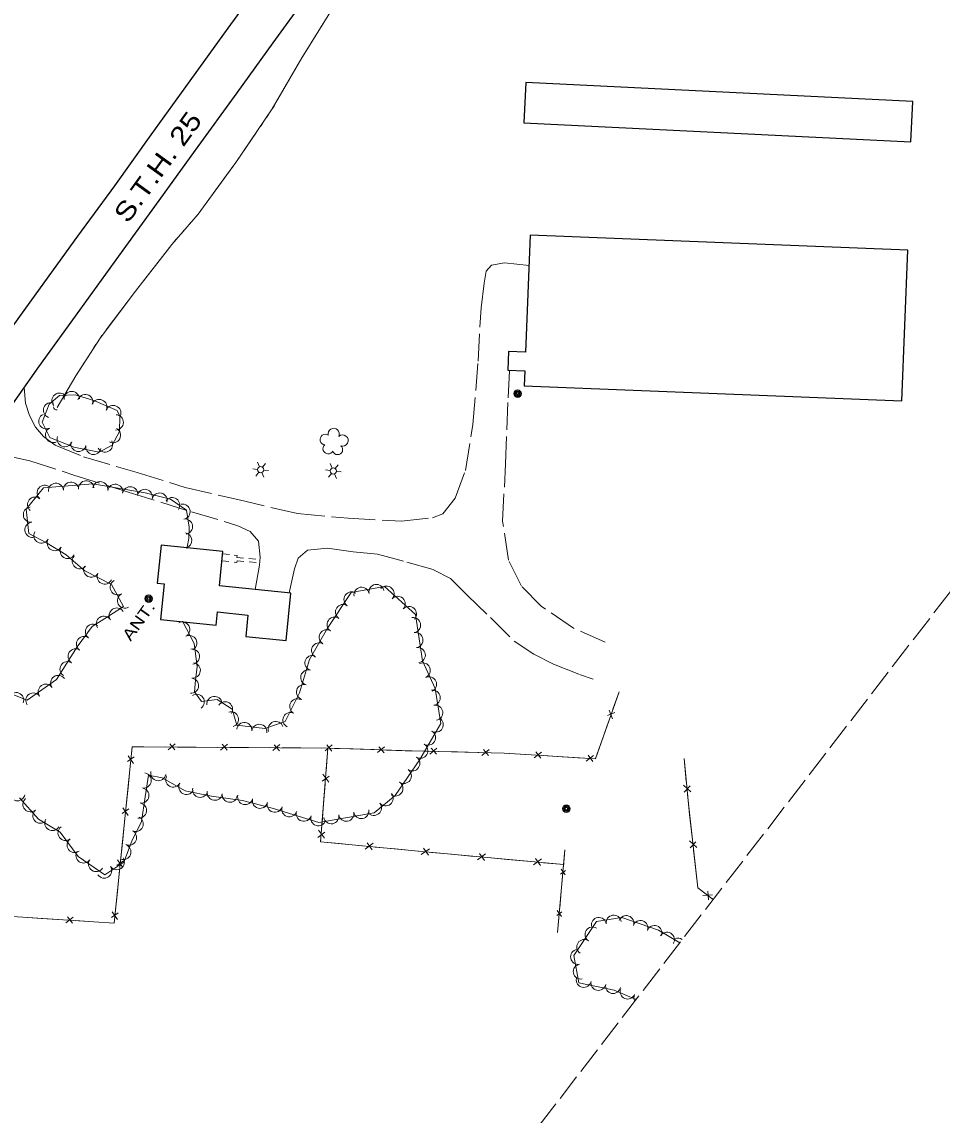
# Model space of a CAD drawing. Extents: x 299311 to 301657, y 49513 to 51866.
# Drawn here: x 300509 to 300996, y 50034 to 50612 of the extents above; entities that cross this region are included whole.
import ezdxf

# ---------------------------------------------------------------- set-up
doc = ezdxf.new("R2010")
doc.units = 0
doc.header["$LTSCALE"] = 2.4
doc.linetypes.add('LONG_DASHED', pattern=[7.5, 6, -1.5])
doc.linetypes.add('SHORT_DASHED', pattern=[2.7, 1.5, -1.2])
for name, color, linetype, lineweight in [('11', 7, 'Continuous', 25), ('12', 7, 'Continuous', 25), ('14', 7, 'Continuous', 13), ('15', 7, 'Continuous', 13), ('17', 7, 'LONG_DASHED', 13), ('18', 7, 'Continuous', 13), ('19', 7, 'Continuous', 13), ('4', 7, 'Continuous', 13)]:
    doc.layers.add(name, color=color, linetype=linetype, lineweight=lineweight)

msp = doc.modelspace()

# ---------------------------------------------------------------- linework, layer by layer
at = {"layer": '11'}
for points in [[(300449.171, 50372.95), (300462.402, 50391.823), (300478.238, 50414.348), (300497.847, 50441.838), (300516.893, 50468.271), (300538.883, 50498.768), (300558.362, 50525.367), (300577.633, 50552.405), (300598.2, 50580.809), (300618.37, 50608.824), (300640.297, 50638.797)], [(300287.176, 50107.164), (300311.291, 50140.598), (300331.977, 50169.98), (300349.427, 50194.729), (300366.089, 50218.225), (300384.892, 50244.576), (300409.609, 50278.747), (300427.494, 50303.203), (300456.56, 50343.148), (300479.329, 50374.693), (300497.325, 50400.091), (300518.311, 50429.548), (300539.854, 50459.658), (300560.519, 50488.121), (300581.893, 50517.65), (300601.128, 50544.137), (300623.029, 50574.5), (300642.077, 50601.015), (300659.645, 50625.084)]]:
    msp.add_lwpolyline(points, dxfattribs=at)
at = {"layer": '12'}
for points in [[(300774.69, 50558.683), (300979.211, 50548.544), (300980.269, 50569.887), (300775.748, 50580.026)], [(300774.842, 50419.534), (300974.479, 50411.65), (300977.626, 50491.338), (300778.066, 50499.218), (300775.625, 50437.41), (300766.593, 50437.767), (300766.202, 50427.871), (300775.157, 50427.517)], [(300582.61, 50296.002), (300612.086, 50293.017), (300612.79, 50299.969), (300628.819, 50298.346), (300627.674, 50287.037), (300648.976, 50284.88), (300651.516, 50309.965), (300613.769, 50313.787), (300615.615, 50332.011), (300582.846, 50335.33), (300580.806, 50315.187), (300584.515, 50314.811)]]:
    msp.add_lwpolyline(points, close=True, dxfattribs=at)
at = {"layer": '14'}
for p, q in [((300633.935, 50375.396), (300631.367, 50375.763)), ((300634.556, 50373.921), (300632.982, 50371.848)), ((300634.933, 50376.773), (300633.915, 50379.182)), ((300636.538, 50376.53), (300638.061, 50378.538)), ((300637.199, 50374.972), (300639.693, 50374.714)), ((300672.327, 50374.734), (300669.759, 50375.101)), ((300673.325, 50376.111), (300672.307, 50378.52)), ((300674.93, 50375.868), (300676.453, 50377.876)), ((300675.591, 50374.31), (300678.085, 50374.052)), ((300636.209, 50373.669), (300637.195, 50371.285)), ((300672.948, 50373.259), (300671.374, 50371.186)), ((300674.601, 50373.007), (300675.587, 50370.623))]:
    msp.add_line(p, q, dxfattribs=at)
for centre, radius in [((300771.402, 50415.413), 2.018), ((300771.39, 50415.418), 1.518), ((300771.426, 50415.4), 1.008), ((300771.42, 50415.409), 0.502), ((300635.563, 50375.211), 1.641), ((300673.955, 50374.549), 1.641), ((300576.253, 50306.933), 2.018), ((300576.241, 50306.938), 1.518), ((300576.277, 50306.92), 1.008), ((300576.271, 50306.929), 0.502), ((300797.161, 50195.998), 2.018), ((300797.149, 50196.003), 1.518), ((300797.185, 50195.985), 1.008), ((300797.179, 50195.994), 0.502)]:
    msp.add_circle(centre, radius, dxfattribs=at)
at = {"layer": '15'}
for p, q in [((300825.105, 50257.815), (300821.805, 50248.499)), ((300822.768, 50246.757), (300818.874, 50245.192)), ((300819.794, 50247.989), (300821.592, 50243.438)), ((300819.624, 50242.34), (300815.872, 50231.747)), ((300590.395, 50230.212), (300586.683, 50227.022)), ((300590.204, 50226.998), (300587.45, 50230.164)), ((300618.049, 50230.022), (300614.337, 50226.833)), ((300617.858, 50226.808), (300615.104, 50229.975)), ((300645.703, 50229.833), (300641.991, 50226.643)), ((300645.512, 50226.619), (300642.758, 50229.786)), ((300673.357, 50229.644), (300669.645, 50226.454)), ((300673.127, 50226.392), (300670.455, 50229.628)), ((300815.872, 50231.747), (300812.572, 50222.431)), ((300565.452, 50223.897), (300568.272, 50219.897)), ((300585.001, 50228.522), (300573.764, 50228.599)), ((300601.418, 50228.41), (300591.534, 50228.478)), ((300612.655, 50228.333), (300601.418, 50228.41)), ((300629.072, 50228.221), (300619.188, 50228.288)), ((300640.309, 50228.144), (300629.072, 50228.221)), ((300656.726, 50228.031), (300646.842, 50228.099)), ((300667.963, 50227.954), (300656.726, 50228.031)), ((300670.17, 50215.911), (300671.123, 50227.982)), ((300684.373, 50227.516), (300674.495, 50227.837)), ((300695.605, 50227.15), (300684.373, 50227.516)), ((300701.04, 50228.701), (300697.248, 50225.607)), ((300700.767, 50225.493), (300698.095, 50228.729)), ((300712.013, 50226.616), (300702.135, 50226.938)), ((300728.669, 50227.91), (300724.903, 50224.785)), ((300728.422, 50224.699), (300725.724, 50227.913)), ((300739.659, 50225.917), (300729.778, 50226.156)), ((300750.893, 50225.646), (300739.659, 50225.917)), ((300756.315, 50227.241), (300752.549, 50224.116)), ((300756.069, 50224.031), (300753.37, 50227.245)), ((300778.517, 50224.442), (300767.301, 50225.137)), ((300783.995, 50225.832), (300780.114, 50222.851)), ((300783.628, 50222.634), (300781.052, 50225.947)), ((300794.902, 50223.427), (300785.038, 50224.038)), ((300811.597, 50224.123), (300807.716, 50221.142)), ((300811.23, 50220.924), (300808.654, 50224.237)), ((300568.633, 50223.399), (300565.217, 50220.961)), ((300566.617, 50218.366), (300565.465, 50207.188)), ((300806.118, 50222.733), (300794.902, 50223.427)), ((300860.564, 50210.398), (300859.439, 50222.404)), ((300668.129, 50210.437), (300671.745, 50213.151)), ((300671.568, 50209.983), (300668.428, 50214.219)), ((300565.465, 50207.188), (300564.452, 50197.356)), ((300668.779, 50198.276), (300669.617, 50208.893)), ((300862.948, 50204.821), (300859.143, 50208.441)), ((300859.496, 50204.679), (300862.581, 50207.96)), ((300565.798, 50195.89), (300562.382, 50193.452)), ((300562.617, 50196.388), (300565.437, 50192.388)), ((300667.826, 50186.204), (300668.779, 50198.276)), ((300563.782, 50190.857), (300562.63, 50179.679)), ((300863.642, 50180.885), (300862.307, 50192.869)), ((300665.785, 50180.731), (300669.401, 50183.445)), ((300669.224, 50180.277), (300666.083, 50184.513)), ((300562.63, 50179.679), (300561.617, 50169.847)), ((300689.116, 50176.32), (300677.064, 50177.484)), ((300695.068, 50177.614), (300690.777, 50174.548)), ((300694.554, 50174.184), (300691.903, 50177.847)), ((300866.123, 50175.35), (300862.256, 50178.903)), ((300862.674, 50175.148), (300865.701, 50178.482)), ((300706.724, 50174.62), (300696.124, 50175.644)), ((300718.777, 50173.457), (300706.724, 50174.62)), ((300724.728, 50174.751), (300720.438, 50171.685)), ((300724.223, 50171.328), (300721.554, 50174.978)), ((300736.392, 50171.827), (300725.786, 50172.796)), ((300748.45, 50170.725), (300736.392, 50171.827)), ((300754.395, 50172.05), (300750.12, 50168.962)), ((300753.899, 50168.616), (300751.229, 50172.266)), ((300792.48, 50130.39), (300796.443, 50174.145)), ((300795.638, 50165.255), (300796.443, 50174.145)), ((300865.594, 50163.377), (300864.419, 50173.917)), ((300562.963, 50168.382), (300559.547, 50165.943)), ((300559.782, 50168.879), (300562.602, 50164.879)), ((300766.067, 50169.116), (300755.461, 50170.085)), ((300778.125, 50168.014), (300766.067, 50169.116)), ((300784.07, 50169.338), (300779.796, 50166.25)), ((300783.574, 50165.905), (300780.904, 50169.555)), ((300795.742, 50166.404), (300785.136, 50167.373)), ((300560.947, 50163.348), (300559.795, 50152.17)), ((300794.086, 50161.237), (300796.775, 50163.208)), ((300796.618, 50160.874), (300794.339, 50164.023)), ((300794.462, 50152.268), (300795.17, 50160.086)), ((300559.795, 50152.17), (300558.782, 50142.338)), ((300793.656, 50143.378), (300794.462, 50152.268)), ((300874.518, 50150.414), (300869.278, 50150.081)), ((300872.278, 50147.785), (300871.966, 50152.277)), ((300874.767, 50147.893), (300874.374, 50148.193)), ((300519.666, 50137.898), (300509.803, 50138.531)), ((300530.881, 50137.178), (300519.666, 50137.898)), ((300536.363, 50138.555), (300532.475, 50135.583)), ((300535.988, 50135.358), (300533.42, 50138.677)), ((300547.264, 50136.126), (300537.401, 50136.759)), ((300560.128, 50140.873), (300556.712, 50138.435)), ((300556.947, 50141.37), (300559.767, 50137.37)), ((300792.105, 50139.36), (300794.794, 50141.33)), ((300794.636, 50138.996), (300792.357, 50142.145)), ((300792.48, 50130.39), (300793.188, 50138.209))]:
    msp.add_line(p, q, dxfattribs=at)
for points in [[(300825.105, 50257.815), (300812.538, 50222.335), (300764.322, 50225.321), (300715.715, 50226.496), (300671.678, 50227.929), (300567.676, 50228.641), (300558.07, 50135.432), (300471.877, 50140.966), (300398.833, 50143.747), (300394.186, 50077.12), (300389.671, 50016.169)], [(300573.764, 50228.599), (300567.676, 50228.641), (300567.287, 50224.865)], [(300795.742, 50166.404), (300722.68, 50173.08), (300667.213, 50178.435), (300671.123, 50227.982)], [(300723.247, 50226.314), (300715.715, 50226.496), (300712.013, 50226.616)], [(300767.301, 50225.137), (300764.322, 50225.321), (300757.425, 50225.488)], [(300874.766, 50147.892), (300866.625, 50154.123), (300861.684, 50198.455), (300859.439, 50222.404)], [(300862.307, 50192.869), (300861.684, 50198.455), (300861.219, 50203.418)], [(300677.064, 50177.484), (300667.213, 50178.435), (300667.272, 50179.186)], [(300868.807, 50152.453), (300866.625, 50154.123), (300865.594, 50163.377)], [(300558.112, 50135.839), (300558.07, 50135.432), (300547.264, 50136.126)]]:
    msp.add_lwpolyline(points, dxfattribs=at)
msp.add_arc((300527.543, 50408.446), 1.55, 179.46436, 285.70392, dxfattribs=at)
at = {"layer": '17'}
for points in [[(300510.566, 50418.676), (300511.214, 50410.483), (300513.283, 50403.844), (300516.45, 50397.773), (300520.655, 50392.84), (300526.891, 50388.116), (300541.904, 50382.011), (300570.217, 50373.782), (300595.603, 50365.867), (300623.393, 50359.426), (300655.101, 50351.986), (300681.784, 50349.531), (300709.944, 50347.945), (300726.429, 50349.83), (300731.933, 50351.857), (300738.452, 50360.077), (300743.848, 50374.847), (300747.767, 50399.128), (300750.481, 50432.636), (300752.076, 50460.888), (300753.766, 50473.928), (300754.679, 50480.306), (300757.607, 50483.326), (300764.481, 50484.707), (300777.434, 50483.21)], [(300817.749, 50283.966), (300800.962, 50291.354), (300783.925, 50302.983), (300773.397, 50313.705), (300766.524, 50327.438), (300763.424, 50348.049), (300765.027, 50378.313), (300766.343, 50413.193), (300767.074, 50427.837)], [(300483.26, 50380.24), (300495.509, 50382.187), (300503.125, 50382.224), (300513.523, 50379.935), (300536.672, 50372.41), (300565.475, 50363.31), (300599.051, 50352.904), (300616.281, 50347.907), (300623.501, 50345.537), (300629.991, 50342.574), (300634.341, 50337.408), (300635.297, 50328.904), (300634.879, 50324.791), (300632.563, 50311.884)], [(300650.686, 50310.049), (300653.479, 50322.832), (300655.309, 50328.343), (300660.296, 50332.644), (300670.903, 50333.688), (300684.376, 50331.788), (300697.235, 50330.509), (300712.84, 50326.314), (300726.978, 50322.296), (300735.892, 50317.64), (300744.743, 50308.828), (300756.987, 50297.059), (300769.503, 50284.6), (300779.886, 50277.583), (300790.295, 50272.378), (300804.115, 50266.93), (300811.322, 50264.383)]]:
    msp.add_lwpolyline(points, dxfattribs=at)
at = {"layer": '17', "linetype": 'SHORT_DASHED'}
for points in [[(300615.483, 50330.712), (300621.46, 50330.034), (300623.055, 50329.822), (300622.887, 50328.843), (300635.169, 50327.648)], [(300615.112, 50327.041), (300622.923, 50326.171), (300623.057, 50327.093), (300634.988, 50325.864)]]:
    msp.add_lwpolyline(points, dxfattribs=at)
at = {"layer": '18'}
msp.add_lwpolyline([(300547.311, 50411.905), (300537.475, 50414.764), (300529.196, 50414.438), (300523.712, 50409.944), (300520.077, 50400.444), (300524.134, 50392.17), (300536.823, 50387.165), (300550.138, 50384.544), (300557.073, 50388.193), (300560.867, 50395.433), (300561.164, 50403.562), (300559.65, 50406.596)], close=True, dxfattribs=at)
for points in [[(300596.562, 50333.539), (300596.763, 50334.306), (300597.476, 50338.882), (300597.716, 50344.887), (300596.25, 50353.729), (300587.891, 50359.675), (300574.483, 50362.939), (300546.82, 50367.728), (300520.768, 50365.605), (300511.62, 50354.427), (300512.988, 50341.549), (300522.318, 50336.561), (300532.713, 50330.271), (300542.565, 50321.74), (300556.757, 50314.518), (300563.071, 50302.953), (300554.514, 50297.359), (300546.41, 50292.351), (300538.468, 50281.538), (300527.55, 50264.346), (300511.997, 50253.32), (300497.335, 50259.169)], [(300508.038, 50201.726), (300517.999, 50190.311), (300529.529, 50183.48), (300539.051, 50170.608), (300553.19, 50160.936), (300563.168, 50167.588), (300567.34, 50178.721), (300572.459, 50189.175), (300574.438, 50202.156), (300576.256, 50213.657), (300583.541, 50212.182), (300595.708, 50205.368), (300609.611, 50202.506), (300626, 50200.28), (300641.613, 50196.28), (300666.215, 50188.646), (300695.482, 50193.738), (300706.74, 50202.866), (300719.632, 50221.978), (300730.884, 50240.974), (300727.842, 50259.511), (300721.183, 50274.187), (300717.365, 50298.559), (300701.046, 50313.452), (300683.468, 50310.189), (300670.833, 50291.344), (300661.31, 50274.869), (300656.146, 50257.198), (300648.538, 50241.998), (300637.735, 50238.316), (300622.999, 50240.126), (300620.387, 50248.588), (300612.62, 50253.616), (300604.205, 50252.55), (300600.567, 50257.822), (300601.11, 50263.871), (300602.037, 50271.087), (300600.305, 50283.25), (300594.134, 50295.197)], [(300857.149, 50125.008), (300845.933, 50131.663), (300826.572, 50138.432), (300813.058, 50136.312), (300801.158, 50118.241), (300803.777, 50103.795), (300822.528, 50099.888), (300834.102, 50095.071)]]:
    msp.add_lwpolyline(points, dxfattribs=at)
for centre, radius, start, end in [((300529.235, 50411.734), 4.043, 39.34142, 219.32609), ((300535.675, 50412.576), 4.043, 2.26262, 182.24729), ((300542.838, 50411.002), 4.043, 343.80026, 163.78494), ((300524.731, 50406.687), 4.043, 69.06923, 249.05391), ((300550.187, 50408.364), 4.043, 336.7273, 156.71198), ((300557.614, 50405.169), 4.043, 336.7273, 156.71198), ((300522.237, 50400.845), 4.043, 116.12781, 296.11249), ((300558.926, 50400.254), 4.043, 267.91524, 87.89992), ((300525.796, 50393.586), 4.043, 116.12781, 296.11249), ((300557.444, 50393.459), 4.043, 242.35163, 62.33631), ((300674.149, 50394.17), 2.974, 332.7899, 194.02379), ((300531.929, 50391.37), 4.043, 158.48159, 338.46627), ((300669.701, 50391.154), 2.777, 55.76079, 263.53379), ((300678.841, 50390.67), 2.975, 250.44072, 133.41399), ((300539.183, 50388.857), 4.043, 168.87161, 348.85629), ((300547.116, 50387.295), 4.043, 168.87161, 348.85629), ((300553.213, 50388.553), 4.043, 207.75973, 27.74441), ((300671.267, 50386.341), 2.783, 132.43781, 333.44885), ((300676.277, 50385.779), 2.611, 195.14595, 53.07856), ((300527.284, 50364.028), 4.014, 4.66645, 184.65113), ((300535.284, 50364.68), 4.014, 4.66645, 184.65113), ((300543.283, 50365.332), 4.014, 4.66645, 184.65113), ((300550.705, 50364.924), 4.014, 350.186, 170.17068), ((300521.343, 50362.99), 4.014, 50.711, 230.69568), ((300558.613, 50363.554), 4.014, 350.186, 170.17068), ((300566.522, 50362.185), 4.014, 350.186, 170.17068), ((300574.288, 50360.825), 4.014, 346.32589, 166.31056), ((300582.086, 50358.926), 4.014, 346.32589, 166.31056), ((300516.259, 50356.779), 4.014, 50.711, 230.69568), ((300588.762, 50356.478), 4.014, 324.58231, 144.56699), ((300594.232, 50353.059), 4.014, 279.42164, 99.40632), ((300514.054, 50351.399), 4.014, 96.07132, 276.056), ((300514.902, 50343.418), 4.014, 96.07132, 276.056), ((300595.545, 50345.141), 4.014, 279.42164, 99.40632), ((300519.595, 50340.398), 4.014, 151.87783, 331.86251), ((300595.183, 50337.812), 4.014, 286.5593, 81.13613), ((300526.67, 50336.383), 4.014, 148.82959, 328.81427), ((300533.537, 50332.228), 4.014, 148.82959, 328.81427), ((300539.923, 50326.807), 4.014, 139.11786, 319.10254), ((300545.935, 50322.382), 4.014, 153.03711, 333.02179), ((300553.088, 50318.742), 4.014, 153.03711, 333.02179), ((300559.962, 50313.032), 4.014, 118.64033, 298.62501), ((300683.597, 50306.609), 4.014, 56.16701, 236.15169), ((300688.889, 50309.059), 4.014, 10.52376, 190.50844), ((300696.781, 50310.524), 4.014, 10.52376, 190.50844), ((300702.066, 50309.677), 4.014, 317.62355, 137.60823), ((300563.808, 50305.987), 4.014, 118.64033, 298.62501), ((300707.994, 50304.267), 4.014, 317.62355, 137.60823), ((300559.436, 50298.067), 4.014, 33.18166, 213.16634), ((300679.127, 50299.942), 4.014, 56.16701, 236.15169), ((300713.923, 50298.857), 4.014, 317.62355, 137.60823), ((300546.908, 50289.481), 4.014, 53.71089, 233.69557), ((300552.625, 50293.722), 4.014, 31.72234, 211.70701), ((300594.109, 50290.668), 4.014, 297.32543, 117.31011), ((300674.657, 50293.276), 4.014, 56.16701, 236.15169), ((300716.107, 50293.015), 4.014, 278.91098, 98.89566), ((300597.792, 50283.537), 4.014, 297.32543, 117.31011), ((300670.504, 50286.577), 4.014, 59.97857, 239.96325), ((300717.35, 50285.085), 4.014, 278.91098, 98.89566), ((300542.157, 50283.012), 4.014, 53.71089, 233.69557), ((300666.487, 50279.628), 4.014, 59.97857, 239.96325), ((300537.746, 50276.483), 4.014, 57.58955, 237.57423), ((300599.158, 50276.402), 4.014, 278.11204, 98.09672), ((300662.958, 50273.018), 4.014, 73.71771, 253.70238), ((300718.592, 50277.156), 4.014, 278.91098, 98.89566), ((300533.443, 50269.707), 4.014, 57.58955, 237.57423), ((300599.653, 50269.015), 4.014, 262.68728, 82.67196), ((300721.209, 50269.046), 4.014, 294.41307, 114.39775), ((300528.487, 50262.435), 4.014, 35.34166, 215.32634), ((300598.74, 50260.962), 4.014, 264.87814, 84.86282), ((300660.706, 50265.314), 4.014, 73.71771, 253.70238), ((300724.525, 50261.737), 4.014, 294.41307, 114.39775), ((300521.939, 50257.793), 4.014, 35.34166, 215.32634), ((300658.455, 50257.61), 4.014, 73.71771, 253.70238), ((300726.519, 50254.604), 4.014, 279.32707, 99.31175), ((300506.245, 50253.353), 4.014, 338.2595, 158.24418), ((300515.391, 50253.152), 4.014, 35.34166, 215.32634), ((300601.713, 50252.463), 4.014, 304.61569, 124.60037), ((300611.099, 50251.306), 4.014, 7.22735, 187.21203), ((300616.705, 50248.469), 4.014, 327.09049, 147.07517), ((300654.899, 50250.013), 4.014, 63.41849, 243.40317), ((300619.855, 50243.191), 4.014, 287.16176, 107.14644), ((300651.307, 50242.836), 4.014, 63.41849, 243.40317), ((300727.818, 50246.684), 4.014, 279.32707, 99.31175), ((300626.882, 50237.533), 4.014, 353.00518, 172.98986), ((300643.501, 50238.062), 4.014, 18.82838, 198.81305), ((300728.111, 50240.414), 4.014, 239.36791, 59.35259), ((300634.849, 50236.554), 4.014, 353.00518, 172.98986), ((300724.02, 50233.508), 4.014, 239.36791, 59.35259), ((300719.93, 50226.603), 4.014, 239.36791, 59.35259), ((300715.712, 50219.923), 4.014, 236.00603, 55.99071), ((300573.685, 50210.849), 4.014, 261.02506, 81.00974), ((300581.427, 50214.753), 4.014, 168.56167, 348.54635), ((300589.318, 50211.355), 4.014, 150.75711, 330.74179), ((300711.224, 50213.27), 4.014, 236.00603, 55.99071), ((300572.432, 50202.921), 4.014, 261.02506, 81.00974), ((300596.32, 50207.433), 4.014, 150.75711, 330.74179), ((300603.528, 50205.903), 4.014, 168.37554, 348.36022), ((300706.736, 50206.616), 4.014, 236.00603, 55.99071), ((300506.908, 50204.097), 4.014, 168.59152, 348.5762), ((300513.861, 50198.248), 4.014, 131.11638, 311.10106), ((300611.264, 50204.401), 4.014, 172.27292, 352.2576), ((300619.217, 50203.321), 4.014, 172.27292, 352.2576), ((300627.389, 50202.093), 4.014, 165.63774, 345.62242), ((300635.164, 50200.101), 4.014, 165.63774, 345.62242), ((300701.595, 50201.399), 4.014, 219.04284, 39.02752), ((300519.138, 50192.201), 4.014, 131.11638, 311.10106), ((300571.218, 50194.976), 4.014, 261.33946, 81.32414), ((300643.029, 50198.04), 4.014, 162.76855, 342.75323), ((300650.694, 50195.661), 4.014, 162.76855, 342.75323), ((300688.739, 50194.697), 4.014, 189.87743, 9.86211), ((300695.361, 50196.344), 4.014, 219.04284, 39.02752), ((300525.394, 50188.371), 4.014, 149.36285, 329.34753), ((300569.482, 50187.873), 4.014, 243.9181, 63.90278), ((300658.36, 50193.283), 4.014, 162.76855, 342.75323), ((300666.025, 50190.904), 4.014, 162.76855, 342.75323), ((300672.925, 50191.946), 4.014, 189.87743, 9.86211), ((300680.832, 50193.321), 4.014, 189.87743, 9.86211), ((300532.393, 50183.141), 4.014, 126.49967, 306.48434), ((300565.953, 50180.664), 4.014, 243.9181, 63.90278), ((300537.166, 50176.689), 4.014, 126.49967, 306.48434), ((300541.901, 50171.203), 4.014, 145.63298, 325.61766), ((300562.955, 50173.006), 4.014, 249.46459, 69.44927), ((300548.526, 50166.672), 4.014, 145.63298, 325.61766), ((300559.483, 50167.656), 4.014, 213.69773, 33.68241), ((300552.805, 50163.204), 4.014, 213.69773, 33.68241), ((300814.374, 50134.424), 3.954, 8.92324, 188.90792), ((300822.184, 50135.649), 3.954, 8.92324, 188.90792), ((300828.853, 50135.442), 3.954, 340.73699, 160.72167), ((300836.316, 50132.833), 3.954, 340.73699, 160.72167), ((300810.992, 50129.412), 3.954, 56.64221, 236.62689), ((300843.78, 50130.224), 3.954, 340.73699, 160.72167), ((300806.644, 50122.809), 3.954, 56.64221, 236.62689), ((300850.337, 50126.644), 3.954, 329.32534, 149.31001), ((300856.211, 50123.487), 3.954, 55.07909, 113.56073), ((300803.386, 50117.554), 3.954, 100.28354, 280.26821), ((300804.796, 50109.774), 3.954, 100.28354, 280.26821), ((300806.357, 50105.371), 3.954, 168.23779, 348.22246), ((300814.097, 50103.758), 3.954, 168.23779, 348.22246), ((300821.837, 50102.146), 3.954, 168.23779, 348.22246), ((300829.572, 50099.197), 3.954, 157.41053, 337.39521), ((300836.872, 50096.159), 3.954, 157.41053, 209.63369)]:
    msp.add_arc(centre, radius, start, end, dxfattribs=at)
at = {"layer": '19'}
for p, q in [((300641.827, 50566.237), (300642.776, 50567.886)), ((300638.625, 50561.511), (300639.698, 50563.083)), ((300635.406, 50556.795), (300636.479, 50558.367)), ((300593.614, 50500.216), (300594.864, 50501.647)), ((300597.364, 50504.509), (300598.615, 50505.94)), ((300589.863, 50495.923), (300591.113, 50497.354)), ((300570.579, 50471.159), (300587.445, 50492.991)), ((300547.412, 50439.792), (300548.442, 50441.391)), ((300544.321, 50434.994), (300545.351, 50436.593))]:
    msp.add_line(p, q, dxfattribs=at)
for points in [[(300528.019, 50408.196), (300537.744, 50424.786), (300550.592, 50444.728), (300569.372, 50469.597), (300588.541, 50494.41), (300602.494, 50510.381), (300622.422, 50537.776), (300641.698, 50566.013), (300657.295, 50593.107), (300672.046, 50616.841)], [(300658.504, 50595.052), (300672.046, 50616.841), (300673.168, 50618.423)], [(300644.674, 50571.184), (300657.295, 50593.107), (300658.504, 50595.052)], [(300617.495, 50531.003), (300622.422, 50537.776), (300633.26, 50553.652)], [(300601.115, 50508.802), (300602.494, 50510.381), (300617.495, 50531.003)], [(300553.933, 50449.152), (300569.372, 50469.597), (300570.579, 50471.159)], [(300550.503, 50444.589), (300550.592, 50444.728), (300551.639, 50446.115)], [(300528.019, 50408.196), (300537.744, 50424.786), (300542.26, 50431.796)]]:
    msp.add_lwpolyline(points, dxfattribs=at)
at = {"layer": '4', "linetype": 'LONG_DASHED'}
msp.add_line((300618.12, 49814.518), (301331.18, 50740.757), dxfattribs=at)

# ---------------------------------------------------------------- texts
at = {"layer": '11', "width": 1.2}
msp.add_text('S.T.H. 25', height=10, rotation=54.102, dxfattribs=at).set_placement((300565.328, 50504.998))
at = {"layer": '14', "width": 1.25}
msp.add_text('ANT.', height=6, rotation=54.366, dxfattribs=at).set_placement((300566.767, 50284.136))

doc.saveas('drawing.dxf')
